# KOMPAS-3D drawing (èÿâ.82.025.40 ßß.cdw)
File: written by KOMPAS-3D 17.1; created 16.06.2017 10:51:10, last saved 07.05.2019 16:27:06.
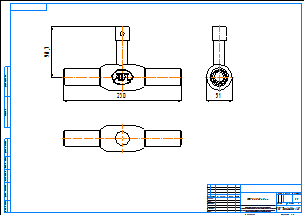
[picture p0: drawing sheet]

Sheet 1: A2, landscape

Title block, sheet 1: name: КШГ.82.025.40 сс; material: Внимание! Данный продукт является объектом авторского права ООО «Торговый Дом АДЛ». / Запрещается изменение, копирование, распространение / (в том числе путем копирования на другие сайты и ресурсы в Интернете) / или любое иное использование информации и объектов без предварительного / согласия правообладателя (ООО «Торговый Дом АДЛ»).; scale: 1:1; sheets: 1; organisation: ООО "Торговый дом АДЛ"; sheet format: A2; stored path: C:\Users\tra\Desktop\2д чертежи\Шаровые краны БИВАЛ\КШ_Бивал_серия_82_85\KOMPAS 2D\КШГ.82.025.40 сс.cdw

Views: Спереди 1, Проекционный вид 2, Проекционный вид 3
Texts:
  Klimkovich
  ADL
Dimensions and other numbers on the sheet: 230; 98,7; 51; 1:1; 1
